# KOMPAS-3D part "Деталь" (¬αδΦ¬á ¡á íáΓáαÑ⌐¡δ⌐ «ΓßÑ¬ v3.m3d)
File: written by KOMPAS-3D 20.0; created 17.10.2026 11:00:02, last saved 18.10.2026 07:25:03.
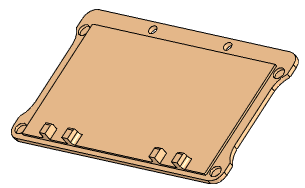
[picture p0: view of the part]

Document properties: Полное имя файла: D:\myProjects\Progect_esp32\box_compas\корпус\крышка на батарейный отсек v3.m3d

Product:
- Part/product: Деталь
    Масса: 0.0729628
  - Body: Тело 1
      Масса: 0.0210038
  - Body: Тело 2
      Масса: 0.0519305

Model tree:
1. Эскиз:1
2. Элемент выдавливания:1
     Расстояние 1 = 0.8
3. Эскиз:2  (with: Элемент выдавливания:1)
4. Элемент выдавливания:2
     Расстояние 1 = 1.6
5. Эскиз:5  (with: Элемент выдавливания:2)
6. Элемент выдавливания:6
     Расстояние 2 = 1.6
7. Эскиз:6  (with: Элемент выдавливания:2, Элемент выдавливания:1)
8. Элемент выдавливания:7
     Расстояние 2 = 1
9. Массив по сетке:2  (with: Элемент выдавливания:7, Эскиз:6)  (4 pattern instances)
     Шаг 1 = 83.2; Угол раствора = -90; Шаг 2 = 36.8
10. Скругление:1  (with: Элемент выдавливания:2)
     Радиус = 4
11. Эскиз:8  (with: Элемент выдавливания:2)
12. Элемент выдавливания:8
     Расстояние 2 = 2.4
13. Смещенная плоскость:1  (with: Элемент выдавливания:2)
     Расстояние = -45
14. Зеркальный массив:1
15. Экземпляр ( 1 )
16. Экземпляр ( 2 )  (with: Элемент выдавливания:8)
17. Эскиз:10  (with: Элемент выдавливания:1)
18. Элемент выдавливания:15
     Расстояние 1 = 3
19. Скругление:8  (with: Элемент выдавливания:15)
     Радиус = 1.2
20. Скругление:9  (with: Элемент выдавливания:15)
     Радиус = 0.8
